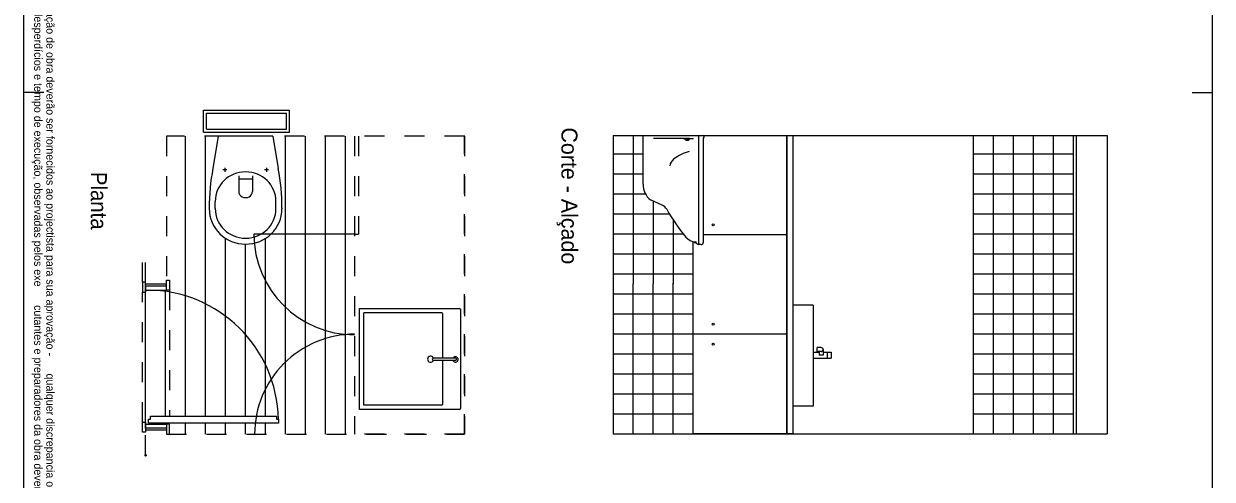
# Model space of a CAD drawing. Extents: x 1280.3 to 1286.2, y -288.3 to -276.7.
# Drawn here: x 1280.28 to 1286.22, y -282.83 to -280.55 of the extents above; entities that cross this region are included whole.
import ezdxf
from ezdxf.enums import TextEntityAlignment as Align

# ---------------------------------------------------------------- set-up
doc = ezdxf.new("R2010")
doc.units = 0
doc.header["$LTSCALE"] = 0.014
doc.header["$PDMODE"] = 32
doc.header["$PDSIZE"] = 0.007
doc.linetypes.add('DOTTED', pattern=[1.5, 0.3, -1.2])
doc.linetypes.add('MEDIUM_DASHED', pattern=[4.5, 3, -1.5])
for name, color, linetype, lineweight in [('1', 7, 'Continuous', 13), ('10', 7, 'Continuous', 13), ('11', 7, 'Continuous', 13), ('13', 7, 'Continuous', 13), ('2', 7, 'Continuous', 13), ('4', 7, 'Continuous', 13), ('62', 7, 'Continuous', 13)]:
    doc.layers.add(name, color=color, linetype=linetype, lineweight=lineweight)
doc.layers.add('60', color=7, linetype='Continuous')

msp = doc.modelspace()

# ---------------------------------------------------------------- linework, layer by layer
at = {"layer": '1', "linetype": 'MEDIUM_DASHED'}
for p, q in [((1280.99026, -281.11414), (1280.99026, -281.85414)), ((1282.47974, -281.11414), (1280.99026, -281.11414)), ((1282.47974, -282.60414), (1282.47974, -281.11214)), ((1282.47974, -282.60414), (1282.47974, -281.11214)), ((1280.88526, -282.70914), (1280.88526, -282.58414))]:
    msp.add_line(p, q, dxfattribs=at)
at = {"layer": '1', "lineweight": 25}
for p, q in [((1283.22224, -281.11214), (1283.22224, -282.60214)), ((1285.69224, -281.11214), (1285.69224, -282.60214)), ((1283.22224, -282.60214), (1285.69224, -282.60214))]:
    msp.add_line(p, q, dxfattribs=at)
at = {"layer": '1'}
for p, q in [((1283.22224, -281.11214), (1285.69224, -281.11214)), ((1285.52224, -281.11214), (1285.52224, -282.60214)), ((1285.53724, -281.11214), (1285.53724, -282.60214)), ((1280.88526, -281.85414), (1280.88526, -281.74656)), ((1280.99026, -281.85414), (1280.88526, -281.85414)), ((1280.90026, -281.85414), (1280.88526, -281.85414)), ((1280.99026, -281.85414), (1280.98026, -281.85414)), ((1280.99026, -282.58414), (1280.88526, -282.58414)), ((1280.99026, -282.58414), (1280.99026, -282.60414))]:
    msp.add_line(p, q, dxfattribs=at)
at = {"layer": '1', "linetype": 'MEDIUM_DASHED'}
msp.add_lwpolyline([(1280.99026, -282.60414), (1282.47974, -282.60414), (1282.47974, -281.11414)], dxfattribs=at)
at = {"layer": '1'}
msp.add_point((1280.88526, -282.70915), dxfattribs=at)
at = {"layer": '10'}
for p, q in [((1281.08526, -282.51414), (1281.08526, -281.11414)), ((1281.18526, -282.51414), (1281.18526, -281.11414)), ((1281.58526, -282.60414), (1281.58526, -281.11414)), ((1281.68526, -282.60414), (1281.68526, -281.11414)), ((1281.78526, -282.60414), (1281.78526, -281.11414)), ((1281.88526, -282.60414), (1281.88526, -281.11414)), ((1283.32224, -281.11214), (1283.32224, -281.85214)), ((1285.12224, -281.11214), (1285.12224, -282.60214)), ((1285.22224, -281.11214), (1285.22224, -282.60214)), ((1285.32224, -281.11214), (1285.32224, -282.60214)), ((1285.42224, -281.11214), (1285.42224, -282.60214)), ((1283.22224, -281.20214), (1283.37226, -281.20214)), ((1285.02224, -281.20214), (1285.52224, -281.20214)), ((1283.22224, -281.30214), (1283.37226, -281.30214)), ((1285.02224, -281.30214), (1285.52224, -281.30214)), ((1283.22224, -281.40214), (1283.38312, -281.40214)), ((1285.02224, -281.40214), (1285.52224, -281.40214)), ((1283.42224, -281.4392), (1283.42224, -281.85214)), ((1283.22224, -281.50214), (1283.50311, -281.50214)), ((1283.52224, -281.53298), (1283.52224, -281.85214)), ((1285.02224, -281.50214), (1285.52224, -281.50214)), ((1283.22224, -281.60214), (1283.57136, -281.60214)), ((1285.02224, -281.60214), (1285.52224, -281.60214)), ((1281.28526, -282.51414), (1281.28526, -281.62499)), ((1281.38526, -282.51414), (1281.38526, -281.65424)), ((1281.48526, -282.51414), (1281.48526, -281.62498)), ((1283.22224, -281.70214), (1283.62224, -281.70214)), ((1285.02224, -281.70214), (1285.52224, -281.70214)), ((1283.22224, -281.80214), (1283.62224, -281.80214)), ((1283.32224, -282.60214), (1283.32224, -281.85214)), ((1283.42224, -282.60214), (1283.42224, -281.85214)), ((1283.52224, -282.60214), (1283.52224, -281.84956)), ((1285.02224, -281.80214), (1285.52224, -281.80214)), ((1280.88526, -282.54414), (1280.88526, -281.89414)), ((1280.98526, -282.51414), (1280.98526, -281.88414)), ((1283.22224, -281.90214), (1283.62224, -281.90214)), ((1285.02224, -281.90214), (1285.52224, -281.90214)), ((1285.02224, -282.00214), (1285.52224, -282.00214)), ((1285.02224, -282.10214), (1285.52224, -282.10214)), ((1285.02224, -282.20214), (1285.52224, -282.20214)), ((1285.02224, -282.30214), (1285.52224, -282.30214)), ((1285.02224, -282.40214), (1285.52224, -282.40214)), ((1285.02224, -282.50214), (1285.52224, -282.50214)), ((1281.08526, -282.60414), (1281.08526, -282.54914)), ((1281.18526, -282.60414), (1281.18526, -282.54914)), ((1281.28526, -282.60414), (1281.28526, -282.54914)), ((1281.38526, -282.60414), (1281.38526, -282.54914)), ((1281.48526, -282.60414), (1281.48526, -282.54914))]:
    msp.add_line(p, q, dxfattribs=at)
at = {"layer": '10', "lineweight": 25}
for p, q in [((1283.22224, -282.00214), (1283.62224, -282.00214)), ((1283.22224, -282.10214), (1283.62224, -282.10214)), ((1283.22224, -282.20214), (1283.62224, -282.20214)), ((1283.22224, -282.30214), (1283.62224, -282.30214)), ((1283.22224, -282.40214), (1283.62224, -282.40214)), ((1283.22224, -282.50214), (1283.62224, -282.50214))]:
    msp.add_line(p, q, dxfattribs=at)
at = {"layer": '11'}
for p, q in [((1281.17462, -281.09414), (1281.17462, -280.98414)), ((1281.17462, -280.98414), (1281.60462, -280.98414)), ((1281.18962, -280.99914), (1281.58962, -280.99914)), ((1281.18962, -281.07914), (1281.18962, -280.99914)), ((1281.60462, -281.09414), (1281.60462, -280.98414)), ((1281.17462, -281.09414), (1281.60462, -281.09414)), ((1281.2486, -281.11414), (1281.22198, -281.27618)), ((1281.52194, -281.11414), (1281.2486, -281.11414)), ((1281.52194, -281.11414), (1281.54858, -281.27618)), ((1283.57556, -281.12702), (1283.42336, -281.12702)), ((1283.60376, -281.12702), (1283.57556, -281.12702)), ((1283.58616, -281.12952), (1283.58616, -281.13552)), ((1283.59816, -281.13552), (1283.58616, -281.13552)), ((1283.58716, -281.13652), (1283.58616, -281.13552)), ((1283.58716, -281.13652), (1283.58716, -281.12952)), ((1283.59716, -281.13652), (1283.58716, -281.13652)), ((1283.59716, -281.13652), (1283.59716, -281.12952)), ((1283.59816, -281.13552), (1283.59716, -281.13652)), ((1283.59816, -281.12952), (1283.59816, -281.13552)), ((1283.60376, -281.12702), (1283.62416, -281.12702)), ((1283.60576, -281.12952), (1283.60576, -281.12702)), ((1283.65086, -281.65656), (1283.65086, -281.11212)), ((1281.29094, -281.28232), (1281.27094, -281.28232)), ((1281.28094, -281.27232), (1281.28094, -281.29232)), ((1281.35094, -281.31216), (1281.35094, -281.39193)), ((1281.41962, -281.31216), (1281.41962, -281.39185)), ((1281.49962, -281.28232), (1281.47962, -281.28232)), ((1281.48962, -281.27232), (1281.48962, -281.29232)), ((1281.41962, -281.32985), (1281.35094, -281.32985)), ((1283.46686, -281.45942), (1283.40886, -281.43312)), ((1281.20344, -281.47335), (1281.20344, -281.47702)), ((1281.23344, -281.47673), (1281.23344, -281.44064)), ((1281.53712, -281.47673), (1281.53712, -281.44064)), ((1281.5671, -281.47335), (1281.56712, -281.47702)), ((1283.66226, -281.65656), (1283.65086, -281.65656)), ((1284.22224, -281.95866), (1284.12224, -281.95866)), ((1281.95514, -281.97566), (1282.45433, -281.97566)), ((1282.36474, -281.99675), (1281.97623, -281.99674)), ((1281.97624, -282.45896), (1281.97623, -281.99674)), ((1282.36912, -282.00113), (1282.36912, -282.22392)), ((1282.45871, -281.98004), (1282.45871, -282.47566)), ((1284.22224, -282.1935), (1284.25224, -282.1935)), ((1284.26224, -282.17094), (1284.24224, -282.17094)), ((1284.27224, -282.1935), (1284.31224, -282.1935)), ((1284.29224, -282.1935), (1284.29224, -282.2235)), ((1284.31224, -282.1935), (1284.31224, -282.2235)), ((1282.43354, -282.22392), (1282.32403, -282.22392)), ((1282.43354, -282.23518), (1282.32404, -282.23518)), ((1282.36912, -282.23518), (1282.36913, -282.45458)), ((1284.22224, -282.2235), (1284.31224, -282.2235)), ((1284.27224, -282.2235), (1284.31224, -282.2235)), ((1282.36475, -282.45896), (1281.97624, -282.45896)), ((1284.22224, -282.46304), (1284.12224, -282.46304))]:
    msp.add_line(p, q, dxfattribs=at)
for points in [[(1281.18962, -281.07914), (1281.58962, -281.07914), (1281.58962, -280.99914)], [(1283.37226, -281.35522), (1283.37226, -281.11212), (1283.38346, -281.11212), (1283.66126, -281.11212), (1283.67226, -281.11212)], [(1283.60576, -281.12952), (1283.57756, -281.12952), (1283.57756, -281.12702)], [(1283.67226, -281.12482), (1283.67226, -281.21932), (1283.67226, -281.22572), (1283.67226, -281.63196), (1283.67226, -281.64156), (1283.67226, -281.64656)], [(1282.45433, -282.48004), (1281.95515, -282.48004), (1281.95514, -281.97566)], [(1284.26224, -282.19094), (1284.24224, -282.19094), (1284.24224, -282.17094)]]:
    msp.add_lwpolyline(points, dxfattribs=at)
for centre, radius, start, end in [((1283.67224, -281.11763), 0.00548, 285.50495, 90), ((1283.67424, -281.12484), 0.002, 105.50495, 180), ((1283.65785, -281.39919), 0.21524, 104.82501, 128.34006), ((1283.55803, -281.27131), 0.05303, 129.46132, 170.71341), ((1283.46802, -281.35774), 0.09581, 178.48024, 231.89028), ((1283.43671, -281.51747), 0.06538, 34.85375, 62.55324), ((1283.65464, -281.54801), 0.09961, 225.73675, 257.2458), ((1283.63034, -281.65678), 0.01185, 30.60668, 78.73), ((1283.65083, -281.64458), 0.012, 210.93096, 270), ((1283.66224, -281.64658), 0.01, 270, 0), ((1282.36474, -282.00113), 0.00438, 0, 90), ((1282.45433, -281.98004), 0.00438, 0, 90), ((1284.26224, -282.18093), 0.01, 270, 90), ((1282.30962, -282.2292), 0.015, 20.71669, 336.36931), ((1282.32345, -282.22955), 0.00566, 84.0038, 275.98244), ((1282.43413, -282.22999), 0.0135, 202.60913, 153.28007), ((1282.43413, -282.22955), 0.00566, 264.01756, 95.9962), ((1282.36475, -282.45458), 0.00438, 270, 0), ((1282.45433, -282.47566), 0.00438, 270, 0)]:
    msp.add_arc(centre, radius, start, end, dxfattribs=at)
for centre, major_axis, ratio, start_param, end_param in [((1282.604, -281.47337), (-1.40058, 0), 0.867922, 6.1202679, 6.2831864), ((1281.38525, -281.44066), (-0.15184, 0), 0.971435, 3.1415951, 6.2831821), ((1280.16767, -281.47336), (1.39942, 0), 0.868644, 6.2831826, 6.4461011), ((1281.38526, -281.39173), (-0.03434, 0), 0.873689, 6.2831634, 9.4247862), ((1281.38525, -281.47674), (-0.18184, 0), 0.976148, 0.0000016, 3.1415886), ((1281.38525, -281.47674), (-0.15184, 0), 0.971435, 0.0000016, 3.1415886), ((1284.12793, -280.90387), (0, -0.99283), 0.78858, 5.3316057, 5.5171217)]:
    msp.add_ellipse(centre, major_axis=major_axis, ratio=ratio, start_param=start_param, end_param=end_param, dxfattribs=at)
msp.add_point((1283.63266, -281.64516), dxfattribs=at)
at = {"layer": '13'}
for p, q in [((1284.09024, -282.60014), (1284.09024, -281.11214)), ((1284.09224, -282.60014), (1284.09224, -281.11214)), ((1284.12224, -282.60014), (1284.12224, -281.11214)), ((1284.09024, -281.60814), (1283.67226, -281.60814)), ((1283.62224, -282.60014), (1283.62224, -281.6422)), ((1280.87026, -281.84414), (1280.87026, -281.74656)), ((1284.22224, -281.95866), (1284.22224, -282.46304)), ((1284.09024, -282.10414), (1283.62224, -282.10414)), ((1280.89958, -282.52914), (1280.90958, -282.52914)), ((1280.90958, -282.51414), (1281.53958, -282.51414)), ((1280.90958, -282.52914), (1280.90958, -282.51414)), ((1281.53958, -282.51414), (1281.53958, -282.52914)), ((1281.53958, -282.52914), (1281.5493, -282.52914)), ((1281.54958, -282.52914), (1281.54958, -282.54914)), ((1283.62224, -282.60014), (1284.12224, -282.60014))]:
    msp.add_line(p, q, dxfattribs=at)
for points in [[(1280.87026, -281.84414), (1280.87026, -281.89414), (1280.88526, -281.89414), (1280.88526, -281.84414)], [(1281.00526, -281.83414), (1281.00526, -281.88414), (1280.99026, -281.88414), (1280.99026, -281.83414)], [(1280.87026, -282.59414), (1280.87026, -282.54414), (1280.88526, -282.54414), (1280.88526, -282.59414)], [(1281.00526, -282.60414), (1281.00526, -282.55414), (1280.99026, -282.55414), (1280.99026, -282.60414)]]:
    msp.add_lwpolyline(points, close=True, dxfattribs=at)
for points in [[(1280.99026, -281.86414), (1280.88526, -281.86414), (1280.88526, -281.89414)], [(1280.88526, -281.88414), (1280.99026, -281.88414), (1280.99026, -281.86414)], [(1280.99026, -282.57414), (1280.88526, -282.57414), (1280.88526, -282.54414)], [(1280.88526, -282.55414), (1280.99026, -282.55414), (1280.99026, -282.57414)], [(1281.54958, -282.54914), (1280.89958, -282.54914), (1280.89958, -282.52914)]]:
    msp.add_lwpolyline(points, dxfattribs=at)
for centre in [(1283.72224, -281.55815), (1283.72224, -282.05413), (1283.72224, -282.15415)]:
    msp.add_circle(centre, 0.005, dxfattribs=at)
at = {"layer": '2', "linetype": 'MEDIUM_DASHED'}
for p, q in [((1282.47974, -281.11414), (1282.47974, -282.60356)), ((1282.47974, -282.60356), (1281.92974, -282.60356))]:
    msp.add_line(p, q, dxfattribs=at)
at = {"layer": '2'}
for p, q in [((1285.02224, -281.11214), (1285.02224, -282.60214)), ((1284.25224, -282.19094), (1284.25224, -282.2085))]:
    msp.add_line(p, q, dxfattribs=at)
at = {"layer": '2', "linetype": 'MEDIUM_DASHED'}
msp.add_lwpolyline([(1282.47974, -281.11414), (1281.92974, -281.11414), (1281.92974, -282.60356)], dxfattribs=at)
at = {"layer": '2'}
msp.add_lwpolyline([(1284.27224, -282.18094), (1284.27224, -282.2085), (1284.25224, -282.2085)], dxfattribs=at)
at = {"layer": '4', "linetype": 'MEDIUM_DASHED'}
msp.add_line((1281.94974, -281.11414), (1281.94974, -281.60414), dxfattribs=at)
at = {"layer": '4'}
for q in [(1281.42679, -281.60414), (1281.94974, -281.60414)]:
    msp.add_line((1281.92974, -281.60414), q, dxfattribs=at)
at = {"layer": '4', "linetype": 'DOTTED'}
for p, q in [((1280.87026, -282.54414), (1280.87026, -281.89414)), ((1281.00526, -281.88414), (1281.00526, -282.51414))]:
    msp.add_line(p, q, dxfattribs=at)
at = {"layer": '4'}
for centre, radius, start, end in [((1281.92974, -281.60414), 0.50295, 180.00107, 270), ((1281.92974, -282.60356), 0.49942, 90, 180.06761)]:
    msp.add_arc(centre, radius, start, end, dxfattribs=at)
msp.add_ellipse((1280.89458, -282.54278), major_axis=(0, -0.65864), ratio=0.994268, start_param=1.5915119, end_param=3.1415927, dxfattribs=at)
at = {"layer": '62'}
for p, q in [((1280.37656, -280.89607), (1280.27656, -280.89607)), ((1286.11656, -280.89687), (1286.21656, -280.89687))]:
    msp.add_line(p, q, dxfattribs=at)
msp.add_lwpolyline([(1280.27656, -276.69647), (1286.21656, -276.69647), (1286.21656, -288.29607), (1280.27656, -288.29607)], close=True, dxfattribs=at)

# ---------------------------------------------------------------- texts
at = {"layer": '60'}
msp.add_text('Corte - Alçado', height=0.08, rotation=270, dxfattribs=at).set_placement((1282.96383, -281.41283), align=Align.CENTER)
at = {"layer": '60', "width": 0.95}
msp.add_text('Planta', height=0.08, rotation=270, dxfattribs=at).set_placement((1280.61185, -281.4373), align=Align.CENTER)
at = {"layer": '62'}
for s, p in [('a introdução de alterações com o objectivo de melhorar os métodos construtivos, a redução de custos, desperdícios e tempo de execução, observadas pelos exe', (1280.32856, -281.86613)), ('os desenhos de preparação de obra deverão ser fornecidos ao projectista para sua aprovação -', (1280.38956, -282.21343)), ('cutantes e preparadores da obra deverão ser sugeridas. não poderão no entanto ser implementadas sem o consentimento expresso dos responsáveis pela arquitectura', (1280.32856, -285.94313)), ('qualquer discrepancia ou incoerencia detectada deverá ser comunicada aos responsáveis pela arquitectura com o objectivo de ser analizada e corrigida -', (1280.38956, -285.94312))]:
    msp.add_text(s, height=0.04, rotation=270, dxfattribs=at).set_placement(p, align=Align.RIGHT)

doc.saveas('drawing.dxf')
